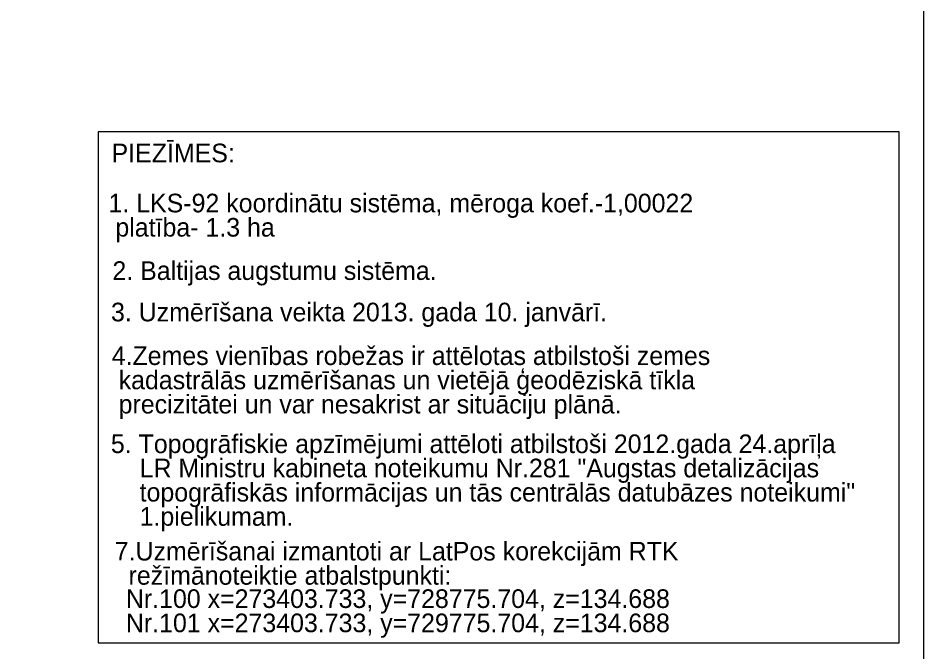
# Model space of a CAD drawing. Extents: x 728710 to 728960, y 272811 to 273475.
# Drawn here: x 728910.93 to 728959.52, y 272834.81 to 272868.82 of the extents above; entities that cross this region are included whole.
import ezdxf

# ---------------------------------------------------------------- set-up
doc = ezdxf.new("R2010")
doc.units = 0
doc.layers.add('RAMI_PLAN_####_TKST_#', color=7, linetype='Continuous')

msp = doc.modelspace()

# ---------------------------------------------------------------- linework, layer by layer
at = {"layer": 'RAMI_PLAN_####_TKST_#'}
for points in [[(728709.938, 272811.037), (728959.516, 272811.036), (728959.516, 273202.048), (728709.939, 273202.048)], [(728915.221, 272835.303), (728958.199, 272835.303), (728958.199, 272862.711), (728915.221, 272862.711)]]:
    msp.add_lwpolyline(points, close=True, dxfattribs=at)

# ---------------------------------------------------------------- texts
for s, rotation, p in [('PIEZĪMES:', 359.9999, (728915.94, 272861.081)), ('1. LKS-92 koordinātu sistēma, mēroga koef.-1,00022', 359.9999, (728915.774, 272858.394)), (' platība- 1.3 ha', 359.9999, (728915.774, 272857.094)), ('2. Baltijas augstumu sistēma.', 359.9999, (728915.987, 272854.769)), ('3. Uzmērīšana veikta 2013. gada 10. janvārī.', 359.9999, (728915.911, 272852.546)), ('4.Zemes vienības robežas ir attēlotas atbilstoši zemes', 359.9999, (728915.948, 272850.204)), (' kadastrālās uzmērīšanas un vietējā ģeodēziskā tīkla ', 359.9999, (728915.948, 272848.904)), (' precizitātei un var nesakrist ar situāciju plānā.', 359.9999, (728915.948, 272847.604)), ('5. Topogrāfiskie apzīmējumi attēloti atbilstoši 2012.gada 24.aprīļa ', 360, (728915.903, 272845.478)), ('    LR Ministru kabineta noteikumu Nr.281 "Augstas detalizācijas', 360, (728915.96, 272844.178)), ('    topogrāfiskās informācijas un tās centrālās datubāzes noteikumi" ', 360, (728915.96, 272842.878)), ('    1.pielikumam.', 360, (728915.96, 272841.578)), ('7.Uzmērīšanai izmantoti ar LatPos korekcijām RTK ', 359.9999, (728916.11, 272839.716)), ('  režīmānoteiktie atbalstpunkti:', 359.9999, (728916.11, 272838.416)), ('Nr.100 x=273403.733, y=728775.704, z=134.688', 359.9999, (728916.708, 272837.168)), ('Nr.101 x=273403.733, y=729775.704, z=134.688', 359.9999, (728916.708, 272835.868))]:
    msp.add_text(s, height=1, rotation=rotation, dxfattribs=at).set_placement(p)

doc.saveas('drawing.dxf')
